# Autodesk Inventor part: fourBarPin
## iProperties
Created: 2008-10
Part Number: fourBarPin
Document SubType Name: Modeling
Designer: Lochan
Density: 1 g/cm^3
Mass: 1.46754 g
Surface Area: 13.2493 cm^2
Volume: 1.46754 cm^3
Author: Lochan
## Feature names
1. Extrusion1
2. Extrusion2
